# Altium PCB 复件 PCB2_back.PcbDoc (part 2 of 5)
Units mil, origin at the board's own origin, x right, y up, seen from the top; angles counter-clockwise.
Board outline 6299 x 3937 mil, 4 copper layers (TopLayer, GROUND, VCC, BottomLayer); 290 components, 470 nets, 2252 pads, 827 vias.
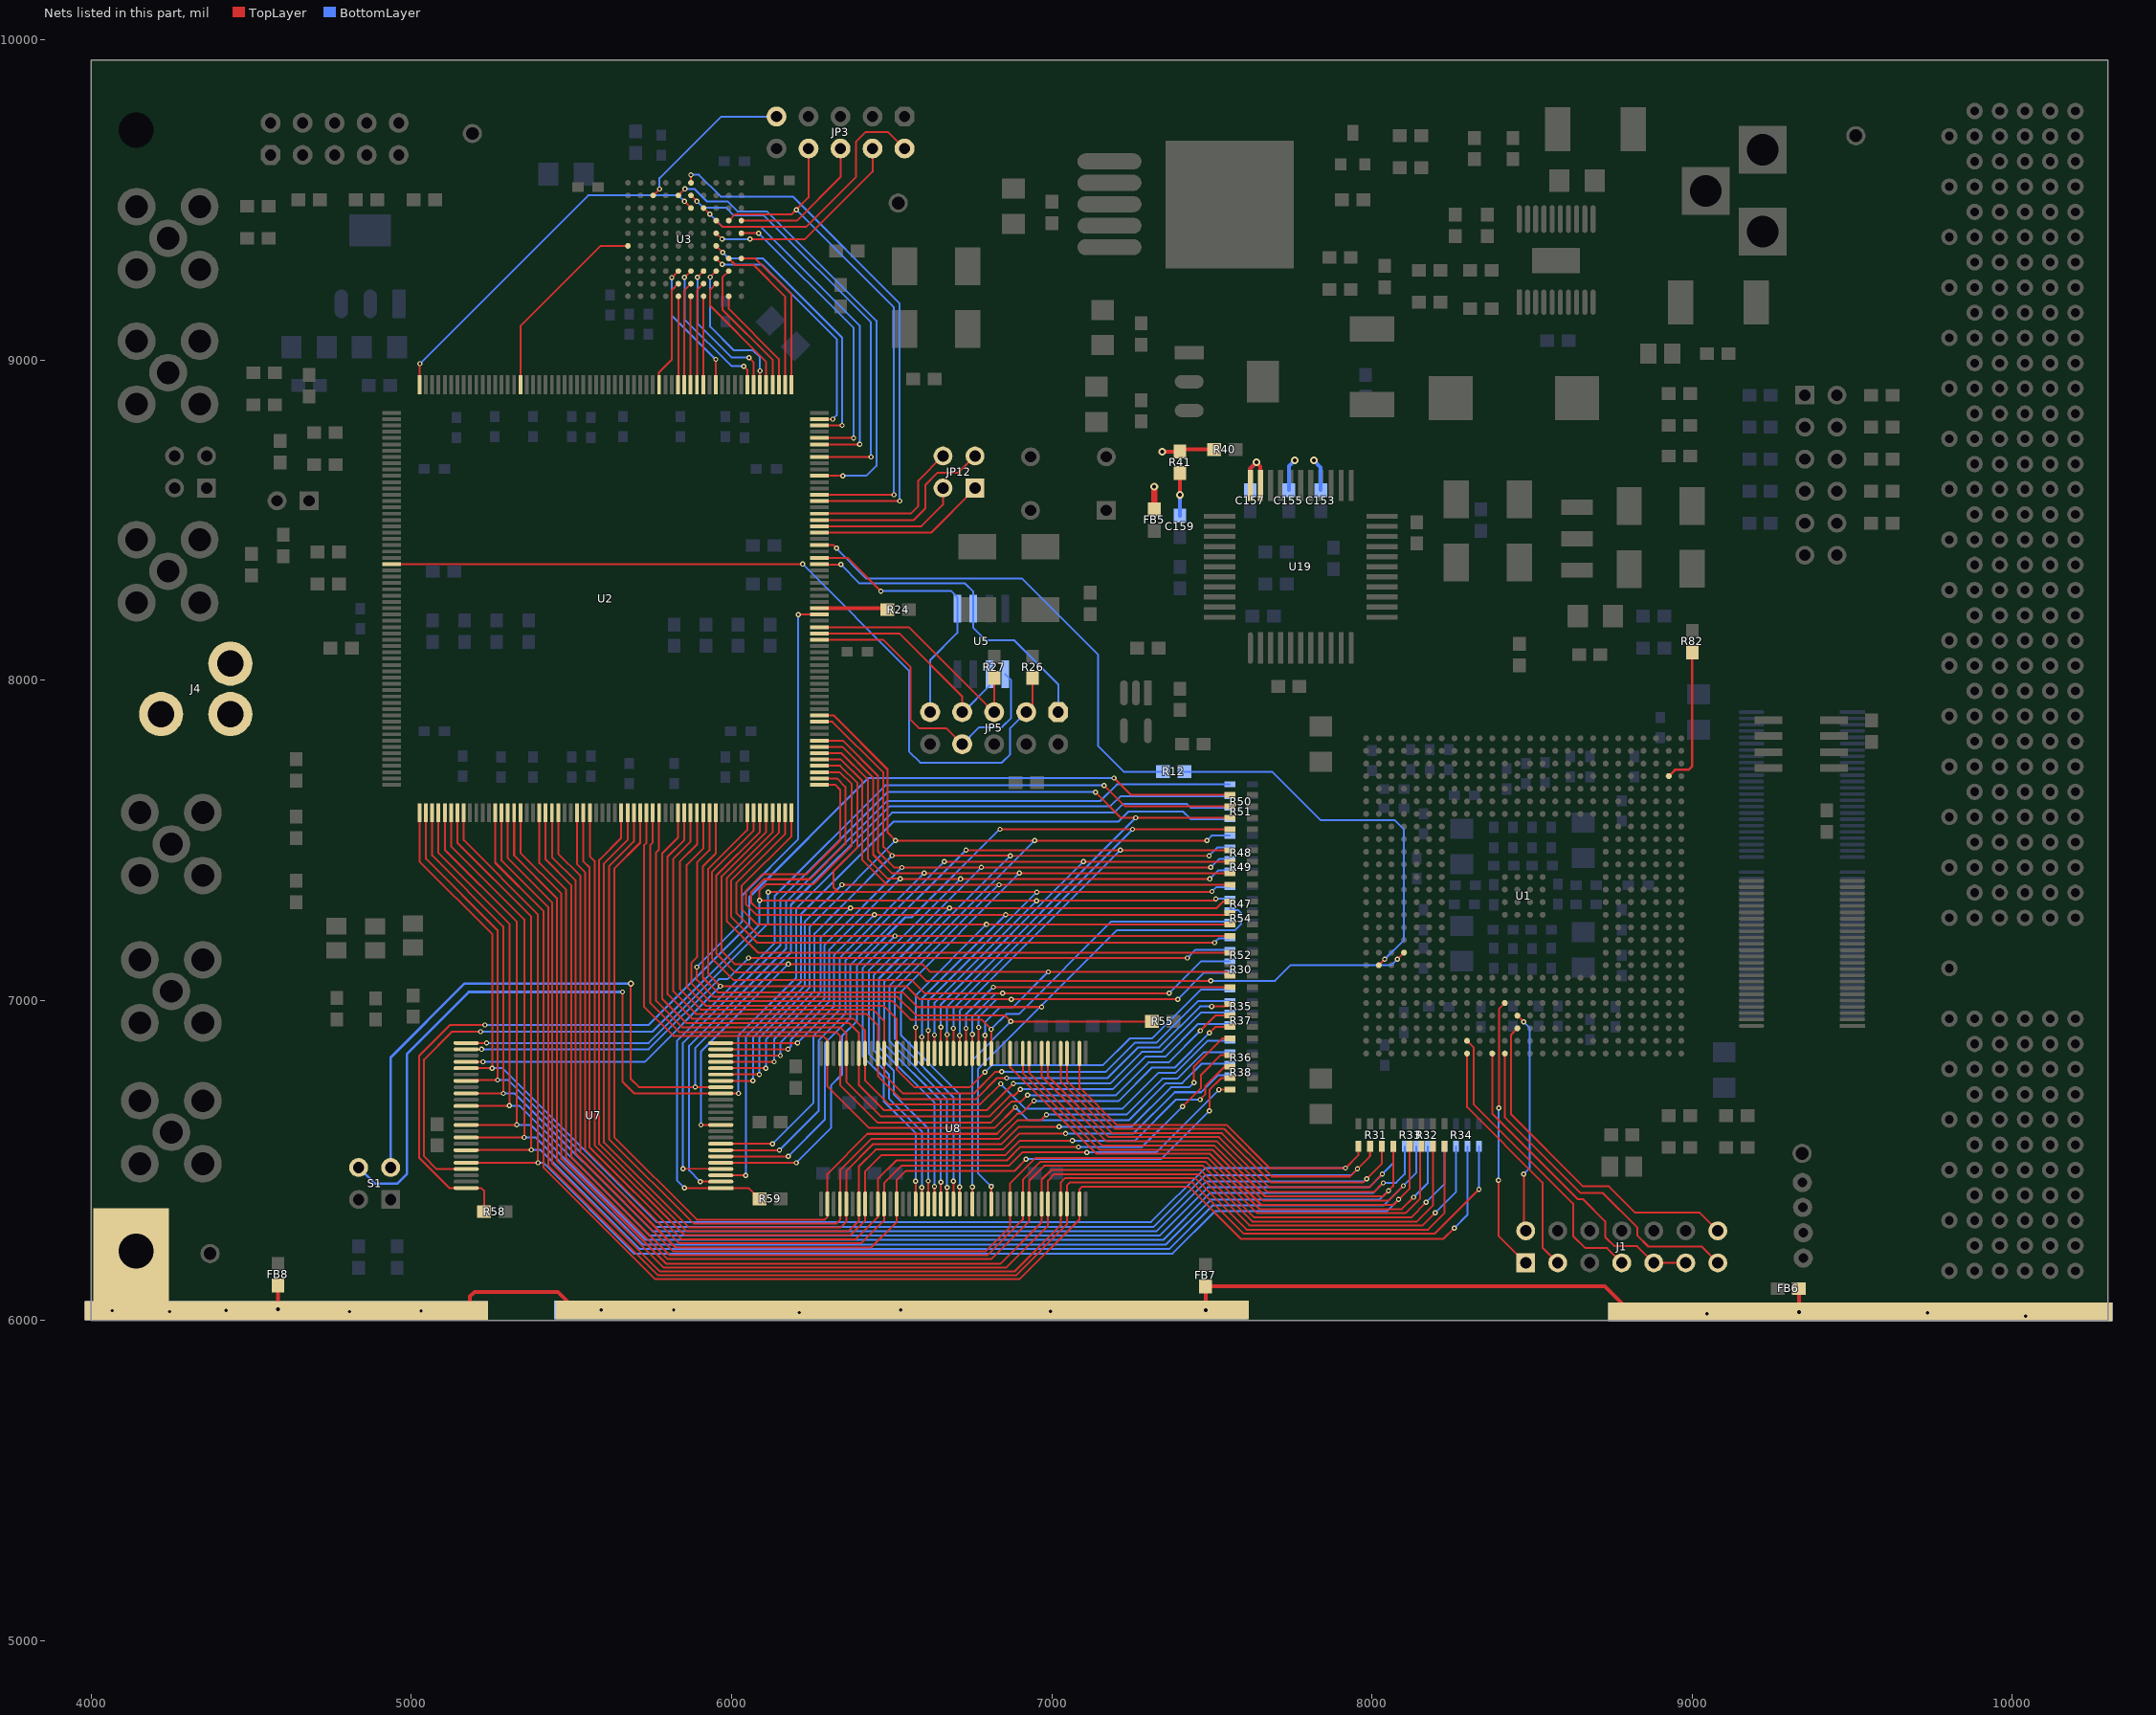
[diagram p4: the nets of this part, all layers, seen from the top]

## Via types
v1: diameter 16, hole 8, TopLayer to BottomLayer, 408 vias
v2: diameter 20, hole 10, TopLayer to BottomLayer, 220 vias
v3: diameter 24, hole 12, TopLayer to BottomLayer, 196 vias
v4: diameter 56.69, hole 56.69, TopLayer to BottomLayer, 2 vias
v5: diameter 20, hole 0, TopLayer to BottomLayer, 1 vias

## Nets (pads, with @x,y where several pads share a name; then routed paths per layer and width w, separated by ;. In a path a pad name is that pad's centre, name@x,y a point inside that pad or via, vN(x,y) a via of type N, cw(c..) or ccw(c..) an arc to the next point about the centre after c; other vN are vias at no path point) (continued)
101_RXST2: U2.104 U3.F1 | length 622.6
  TopLayer w6: U2.104@5340.25,8922.31 5340.25,9105.25 5591.15,9356.15 U3.F1@5676,9356.15
101_SCSEL: U2.63 U3.K9 | length 341.1
  TopLayer w6: U3.K9@5990.96,9198.67 5990.96,9159.04 6147.34,9002.66 U2.63@6147.34,8922.31
101_SDASEL: U2.120 U3.C6 | length 1147.2
  TopLayer w6: U2.120@5025.29,8922.31 5026,8923.02 v1(5026,8988) ; v1(5852.11,9495) U3.C6@5872.85,9474.26
  BottomLayer w6: v1(5026,8988) 5552,9514 5833.11,9514 v1(5852.11,9495)
101_SPDSEL: U2.55 U3.C7 | length 1136.3
  TopLayer w6: U3.C7@5912.22,9474.26 v1(5931.48,9455) ; U2.55@6274.31,8736.28 v1(6400,8736.28)
  BottomLayer w6: v1(5931.48,9455) 5971.48,9415 6092,9415 6400,9107 v1(6400,8736.28)
101_T\R\S\T\Z\: JP3.8 U2.47 U3.D9 | length 1680.7
  TopLayer w6: U3.D9@5990.96,9434.89 6011.07,9455 6188,9455 6240,9507 JP3.8@6240,9660 ; U2.47@6274.31,8578.8 v1(6507,8578.8)
  BottomLayer w6: v1(6202,9469) 6506,9165 ; v1(6507,8578.8) 6507,9165
101_T\X\R\S\T\: U2.64 U3.H9 | length 428.3
  TopLayer w6: U3.H9@5990.96,9277.41 5971,9257.45 5971,9157 6127.65,9000.35 U2.64@6127.65,8922.31
101_TCK: JP3.4 U3.E8 | length 655.5
  TopLayer w6: U3.E8@5951.59,9395.52 v1(5970.11,9377) ; v1(6057,9377) 6229,9377 6440,9588 JP3.4@6440,9660
  BottomLayer w6: v1(5970.11,9377) v1(6057,9377)
101_TDI: JP3.6 U3.D10 | length 455
  TopLayer w6: U3.D10@6030.33,9434.89 6203.89,9434.89 6340,9571 JP3.6@6340,9660
101_TDO: JP3.9 U3.B3 | length 507.3
  TopLayer w6: U3.B3@5754.74,9513.63 v1(5774.63,9533.52)
  BottomLayer w6: v1(5774.63,9533.52) 5774.63,9567.63 5967,9760 JP3.9@6140,9760
101_TMS: JP3.2 U3.D8 | length 804.8
  TopLayer w6: U3.D8@5951.59,9434.89 5971.48,9415 6232,9415 6389,9572 6389,9682 6418,9711 6489,9711 JP3.2@6540,9660
101_TXCKSEL: U2.56 U3.E10 | length 923.2
  TopLayer w6: U3.E10@6030.33,9395.52 v1(6084.48,9395.52) ; U2.56@6274.31,8755.97 v1(6381,8755.97)
  BottomLayer w6: v1(6084.48,9395.52) 6381,9099 v1(6381,8755.97)
101_TXCLK: U2.66 U3.H8 | length 461.7
  TopLayer w6: v1(5933,9258.82) U3.H8@5951.59,9277.41 ; U2.66@6088.28,8922.31 v1(6088.28,8965.72)
  BottomLayer w6: v1(5933,9258.82) 5933,9104 6007,9030 6066,9030 6088.28,9007.72 v1(6088.28,8965.72)
101_TXCLKO+: U2.62 U3.G9 | length 500.9
  TopLayer w6: U3.G9@5990.96,9316.78 6011.74,9296 6069,9296 6167.02,9197.98 U2.62@6167.02,8922.31
101_TXCLKO-: U2.61 U3.G10 | length 485
  TopLayer w6: U3.G10@6030.33,9316.78 6074.22,9316.78 6186.71,9204.29 U2.61@6186.71,8922.31
101_TXCT0: U2.82 U3.J5 | length 340.7
  TopLayer w6: U2.82@5773.32,8922.31 5773.32,8961.32 5813,9001 5813,9217.56 U3.J5@5833.48,9238.04
101_TXCT1: U2.73 U3.H5 | length 420.5
  TopLayer w6: v1(5813,9256.93) U3.H5@5833.48,9277.41 ; U2.73@5950.49,8922.31 v1(5950.49,9001.51)
  BottomLayer w6: v1(5813,9256.93) 5813,9139 v1(5950.49,9001.51)
101_TXD0: U2.65 U3.J8 | length 395.9
  TopLayer w6: U3.J8@5951.59,9238.04 5933,9219.45 5933,9169 6107.97,8994.03 U2.65@6107.97,8922.31
101_TXD1: U2.75 U3.K7 | length 276.8
  TopLayer w6: U2.75@5911.12,8922.31 5911.12,9197.57 U3.K7@5912.22,9198.67
101_TXD2: U2.76 U3.J7 | length 324.3
  TopLayer w6: U2.76@5891.43,8922.31 5891.43,9217.25 U3.J7@5912.22,9238.04
101_TXD3: U2.67 U3.H7 | length 466.8
  TopLayer w6: v1(5893,9258.19) U3.H7@5912.22,9277.41 ; v1(6054,9007) 6068.6,8992.4 U2.67@6068.6,8922.31
  BottomLayer w6: v1(5893,9258.19) 5893,9115 6001,9007 v1(6054,9007)
101_TXD4: U2.77 U3.K6 | length 276.8
  TopLayer w6: U2.77@5871.75,8922.31 5871.75,9197.57 U3.K6@5872.85,9198.67
101_TXD5: U2.78 U3.J6 | length 324.3
  TopLayer w6: U2.78@5852.06,8922.31 5852.06,9217.25 U3.J6@5872.85,9238.04
101_TXD6: U2.68 U3.H6 | length 466.7
  TopLayer w6: v1(5853,9257.56) U3.H6@5872.85,9277.41 ; v1(6038,8980) 6048.91,8969.09 U2.68@6048.91,8922.31
  BottomLayer w6: v1(5853,9257.56) 5853,9127 6000,8980 v1(6038,8980)
101_TXD7: U2.79 U3.K5 | length 278.4
  TopLayer w6: U2.79@5832.38,8922.31 5833.48,8923.41 U3.K5@5833.48,9198.67 U3.K5@5832.38,9197.57
101_TXMODE0: U2.53 U3.B6 | length 1307.2
  TopLayer w6: U3.B6@5872.85,9513.63 v1(5891.48,9495) ; U2.53@6274.31,8696.91 v1(6435,8696.91)
  BottomLayer w6: v1(5891.48,9495) 5910.48,9476 5982,9476 6007,9451 6101,9451 6435,9117 v1(6435,8696.91)
101_TXMODE1: U2.46 U3.A6 | length 1711
  TopLayer w6: U3.A6@5872.85,9553 v1(5872.85,9577.85) ; U2.46@6274.31,8559.12 v1(6525,8559.12)
  BottomLayer w6: v1(5872.85,9577.85) 5898,9577.85 5965.85,9510 6191,9510 6525,9176 v1(6525,8559.12)
101_TXOP: U2.59 U3.G8 | length 777.4
  TopLayer w6: U3.G8@5951.59,9316.78 v1(5970.37,9298) ; U2.59@6274.31,8815.02 v1(6316.02,8815.02)
  BottomLayer w6: v1(5970.37,9298) 6095,9298 6328,9065 6328,8827 v1(6316.02,8815.02)
101_TXPER: U2.58 U3.F8 | length 857.3
  TopLayer w6: U3.F8@5951.59,9356.15 v1(5971.74,9336) ; U2.58@6274.31,8795.34 v1(6345,8795.34)
  BottomLayer w6: v1(5971.74,9336) 5990.74,9317 6098,9317 6345,9070 v1(6345,8795.34)
101_TXRATE: U2.50 U3.B5 | length 1441.1
  TopLayer w6: U3.B5@5833.48,9513.63 v1(5853.7,9533.85) ; U2.50@6274.31,8637.86 v1(6346.86,8637.86)
  BottomLayer w6: v1(5853.7,9533.85) 5883.15,9533.85 5922,9495 5987,9495 6018,9464 6110,9464 6452,9122 6452,8669 6420.86,8637.86 v1(6346.86,8637.86)
AGND: C153.1 C155.1 C157.1 C159.1 FB5.1 J4.2 R41.1 U19.32 U19.33 | length 657.9
  TopLayer w12: v3(7400,8578) R41.1@7400,8646.54 ; U19.33@7620,8607.87 7620,8661 v3(7639,8680) 7651.5,8667.5 U19.32@7651.5,8607.87
  TopLayer w20: FB5.1@7320,8533.46 v3(7320,8604)
  BottomLayer w12: C159.1@7400,8513.46 v3(7400,8578) ; C157.1@7620,8593.46 7620,8661 v3(7639,8680) ; C155.1@7740,8593.46 7740,8669 v3(7758,8687) ; v3(7818,8686) 7840,8664 C153.1@7840,8593.46
AOE#: R52.6 U2.234 U8.19 | length 2452.6
  TopLayer w6: U2.234@6068.6,7585.69 6068.6,7530.6 5938,7400 5938,7131 6005,7064 6561,7064 6603,7022 v1(7366,7022) ; U8.19@6751.67,6834 v1(6751.67,6893.67)
  BottomLayer w6: v1(6751.67,6893.67) 6751.67,6948.67 6825,7022 v1(6846,7022) ; v1(7366,7022) 7466,7122 R52.6@7555.84,7122
ARE#: R52.5 U2.233 U7.28 U8.18 | length 3381.2
  TopLayer w6: U7.28@5170.72,6807.7 v1(5223.7,6807.7) ; U2.233@6048.91,7585.69 6048.91,7531.91 5926,7409 5926,7083 v1(5965,7044) 6546,7044 6587,7003 v1(7393,7003) ; U8.18@6771.35,6834 v1(6771.35,6915.35)
  BottomLayer w6: v1(5223.7,6807.7) 5728.7,6807.7 v1(5965,7044) ; v1(6771.35,6915.35) 6771.35,6947.35 6827,7003 v1(6873,7003) ; v1(7393,7003) 7476,7086 R52.5@7555.84,7086
AS_CONFDN: JP5.3 R26.1 U2.145 | length 2615.7
  TopLayer w6: U2.145@4937.69,8362.27 v1(6221.73,8362.27) ; JP5.3@6920,7900 6940,7920 R26.1@6940,8006.54
  BottomLayer w6: v1(6221.73,8362.27) 6554,8030 6554,7777 6589,7742 6844,7742 6870,7768 6870,7850 JP5.3@6920,7900
AS_DCLK: JP5.1 U2.36 U5.6 | length 1054.3
  TopLayer w6: U2.36@6274.31,8362.27 6275.57,8361 v1(6341,8361)
  BottomLayer w6: v1(6341,8361) 6400,8302 6729,8302 6755,8276 6755,8163 6794,8124 6883,8124 7020,7987 JP5.1@7020,7900
AS_NCONFIG: JP5.5 R27.1 U2.26 | length 762.2
  TopLayer w6: U2.26@6274.31,8165.42 6553.58,8165.42 6819,7900 JP5.5@6820,7900 R27.1@6820,8006.54
AWE#: R30.7 U2.236 U7.11 U8.17 | length 3145.4
  TopLayer w6: v1(5904.15,6610.85) U7.11@5966,6610.85 ; U2.236@6107.97,7585.69 6107.97,7525.97 5969,7387 5969,7154 6010,7113 6595,7113 6619,7089 7543.84,7089 R30.7@7555.84,7077 ; U8.17@6791.04,6834 v1(6791.04,6891.04)
  BottomLayer w6: v1(5904.15,6610.85) 5904.15,6840.15 v1(6177,7113) ; v1(6791.04,6891.04) 6791.04,6931.04 6838.94,6978.94 6878.94,6978.94 v1(6989,7089)
BE0#: R47.5 U2.227 U8.16 | length 2511.8
  TopLayer w6: U2.227@5930.8,7585.69 5930.8,7468.8 5892,7430 5892,7135 5874,7117 5874,7054 5930,6998 6501,6998 6559,6940 6780.45,6940 v1(6810.73,6909.73) U8.16@6810.73,6834
  BottomLayer w6: v1(6810.73,6909.73) 6859,6958 6898,6958 7186,7246 R47.5@7555.84,7246
BE1#: R47.6 U2.228 U8.71 | length 3156
  TopLayer w6: U2.228@5950.49,7585.69 5950.49,7458.49 5910,7418 5910,7071 5956,7025 6534,7025 6580,6979 v1(6968,6979) ; U8.71@6810.73,6364 v1(6810.73,6418.73)
  BottomLayer w6: v1@6816,6424 v1(6810.73,6418.73) 6770,6459.45 6770,6786 7203,7219 7572,7219 7591,7238 7591,7273 7582,7282 R47.6@7555.84,7282
BE2#: R54.7 U2.240 U8.28 | length 2404.7
  TopLayer w6: U2.240@6186.71,7585.69 6186.71,7512.71 6031,7357 6031,7285 6079,7237 R54.7@7555.84,7237 ; U8.28@6574.51,6834 v1(6574.51,6915.51)
  BottomLayer w6: v1(6574.51,6915.51) 6574.51,7015.51 v1(6796,7237)
BE3#: R54.8 U2.239 U8.59 | length 2895.1
  TopLayer w6: U2.239@6167.02,7585.69 6167.02,7519.02 6014,7366 6014,7273 6086,7201 R54.8@7555.84,7201 ; U8.59@6574.51,6364 v1(6574.51,6435.51)
  BottomLayer w6: v1(6510,7201) 6409,7100 6409,6825 6475,6759 6475,6685 6574.51,6585.49 v1(6574.51,6435.51)
CE0#: R30.8 U8.20 | length 981.1
  TopLayer w6: U8.20@6731.98,6834 v1(6731.98,6912.31) ; v1(6817,7041) R30.8@7555.84,7041
  BottomLayer w6: v1(6731.98,6912.31) 6731.98,6955.98 v1(6817,7041)
CE1#: R52.7 U7.26 | length 2513.9
  TopLayer w6: U7.26@5170.72,6847.07 v1(5219,6847) ; v1(6053,7132) v1(7423,7132)
  BottomLayer w6: v1(5219,6847) 5576.07,6847.07 5741.07,6847.07 5960,7066 5987,7066 v1(6053,7132) ; v1(7423,7132) 7449,7158 R52.7@7555.84,7158
CE2#: R52.8 U2.238 | length 1983.2
  TopLayer w6: U2.238@6147.34,7585.69 6147.34,7523.34 5998,7374 5998,7262 6080,7180 v1(7508,7180)
  BottomLayer w6: v1(7508,7180) 7522,7194 R52.8@7555.84,7194
CE3#: R30.5 U2.237 | length 2009.8
  TopLayer w6: U2.237@6127.65,7585.69 6127.65,7524.65 5985,7382 5985,7246 6082,7149 R30.5@7555.84,7149
CVBS: J4.1 R40.2 R41.2 | length 164.7
  TopLayer w12: v3(7344.54,8713.46) R41.2@7400,8713.46 7406.54,8720 R40.2@7506.54,8720
DATA: JP5.7 U2.25 U5.2 | length 730.8
  TopLayer w6: U2.25@6274.31,8145.73 6523.27,8145.73 6720,7949 JP5.7@6720,7900
  BottomLayer w6: JP5.7@6720,7900 6723,7900 6805,7982 U5.2@6805,8017.64
DSP_CLKIN: R82.2 U1.AC2 | length 441.7
  TopLayer w8: U1.AC2@8926.63,7700.14 8946.49,7720 8989,7720 9000,7731 R82.2@9000,8086.54
DSP_T\R\S\T\: J1.2 U1.D14 | length 697.7
  TopLayer w6: U1.D14@8454.19,6952.11 v1(8474,6932.3) ; v1(8474,6457) 8474,6286 J1.2@8480,6280
  BottomLayer w6: v1(8474,6457) 8492,6475 8492,6914.3 v1(8474,6932.3)
DSP_TCLK: J1.9 J1.11 U1.A16 | length 1014
  TopLayer w6: U1.A16@8375.45,6834 8375.45,6646.55 8643,6379 8659,6379 8728,6310 8728,6261 8757,6232 8828,6232 J1.9@8880,6180 J1.11@8980,6180
DSP_TDI: J1.3 U1.A18 | length 771.3
  TopLayer w6: U1.A18@8296.71,6834 8296.71,6666.29 8532,6431 8532,6228 J1.3@8580,6180
DSP_TDO: J1.7 U1.B18 | length 933.4
  TopLayer w6: U1.B18@8296.71,6873.37 8317,6853.08 8317,6676 8628,6365 8628,6264 8666,6226 8734,6226 J1.7@8780,6180
DSP_TMS: J1.1 U1.E15 | length 854.9
  TopLayer w6: v1(8395,6438) 8395,6265 J1.1@8480,6180 ; v1(8396,6664) 8396,6972.66 U1.E15@8414.82,6991.48
  BottomLayer w6: v1(8395,6438) 8395,6663 v1(8396,6664)
EA03: R47.7 U2.3 U7.45 U8.25 | length 4512.2
  TopLayer w6: U7.45@5170.72,6473.06 5078.94,6473.06 5039,6513 5039,6815 5126,6902 v1(5216,6902) ; v1(6087,7312) 6087,7343 6106,7362 6254,7362 6375,7483 6375,7675 6337.34,7712.66 U2.3@6274.31,7712.66 ; v1@6088,7311 7506,7311 v1(7512,7317) ; U8.25@6633.56,6834 v1(6633.56,6891.56)
  BottomLayer w6: v1(5216,6902) 5753,6902 6087,7236 v1(6087,7312) ; v1(6633.56,6891.56) 6633.56,6992.56 v1(6952,7311) ; v1(7512,7317) R47.7@7554.84,7317
EA04: R47.8 U2.4 U7.25 U8.26 | length 3807.3
  TopLayer w6: U7.25@5170.72,6866.76 v1(5234.76,6866.76) ; v1(6114,7338) 7498,7338 v1(7500,7340) ; U2.4@6274.31,7732.35 6338.65,7732.35 6393,7678 6393,7478 6318,7403 6318,7353 6333,7338 ; U8.26@6613.88,6834 v1(6613.88,6905.31)
  BottomLayer w6: v1(5234.76,6866.76) 5740.76,6866.76 6114,7240 v1(6114,7338) ; v1(6613.88,6905.31) 6613.88,6998.88 v1(6953,7338) ; v1(7500,7340) 7514,7354 R47.8@7555.84,7354
EA05: R54.6 U2.1 U7.24 U8.27 | length 3440.2
  TopLayer w6: U7.24@5966,6866.76 v1(6205.76,6866.76) ; U2.1@6274.31,7673.29 6323.71,7673.29 6339,7658 6339,7499 6233,7393 6095,7393 6045,7343 6045,7299 6077,7267 7549.84,7267 R54.6@7555.84,7273 ; U8.27@6594.19,6834 v1(6594.19,6885.63)
  BottomLayer w6: v1(6205.76,6866.76) 6319,6980 6319,7140 v1(6446,7267) ; v1(6594.19,6885.63) 6594.19,7005.19 v1(6856,7267)
EA06: R48.5 U2.6 U7.23 U8.60 | length 3691.2
  TopLayer w6: U7.23@5966,6847.07 v1(6176.07,6847.07) ; U2.6@6274.31,7771.72 6343.28,7771.72 6425,7690 6425,7442 6487.1,7379.9 v1(6526.9,7379.9) ; v1@6526.9,7379 v1(7493,7379) ; U8.60@6594.19,6364 v1(6594.19,6415.19)
  BottomLayer w6: v1(6176.07,6847.07) 6185,6856 6185,6877 6305,6997 6305,7158 v1(6526.9,7379.9) ; v1(6594.19,6415.19) 6594.19,6591 6491,6694.19 6491,6769 6428,6832 6428,7092 v1(6715,7379) ; v1(7493,7379) 7520,7406 R48.5@7555.84,7406
EA07: R48.6 U2.8 U7.22 U8.61 | length 3786.6
  TopLayer w6: U7.22@5966,6827.39 v1(6152.39,6827.39) ; U2.8@6274.31,7811.09 6346.91,7811.09 6457,7701 6457,7465 6507.19,7414.81 v1(6531.81,7414.81) ; v1@6531.81,7415 v1(7496,7415) ; U8.61@6613.88,6364 v1(6613.88,6435.88)
  BottomLayer w6: v1(6152.39,6827.39) 6152.39,6868.39 6290,7006 6290,7173 v1(6531.81,7414.81) ; v1(6613.88,6435.88) 6613.88,6599 6506,6706.88 6506,6781 6444,6843 6444,7079 v1(6780,7415) ; v1(7496,7415) 7523,7442 R48.6@7555.84,7442
EA08: R54.5 U2.2 U7.21 U8.62 | length 4002.9
  TopLayer w6: U7.21@5966,6807.7 v1(6132.7,6807.7) ; U2.2@6274.31,7692.98 6329.02,7692.98 6355,7667 6355,7488 6245,7378 6101,7378 6061,7338 6061,7305 6078,7288 7515,7288 7536,7309 R54.5@7555.84,7309 ; U8.62@6633.56,6364 v1(6633.56,6418.56)
  BottomLayer w6: v1(6132.7,6807.7) 6132.7,6879 6277,7023.3 6277,7194 v1(6371,7288) ; v1(6633.56,6418.56) 6633.56,6680.44 6460,6854 6460,7068 v1(6680,7288)
EA09: R48.7 U2.11 U7.20 U8.63 | length 3901.4
  TopLayer w6: U7.20@5966,6788.02 v1(6107.02,6788.02) ; U2.11@6274.31,7870.14 6314.86,7870.14 6474,7711 6474,7479 v1(6501,7452) 6870,7451.63 v1(7491,7451) ; U8.63@6653.24,6364 v1(6653.24,6431.76)
  BottomLayer w6: v1(6107.02,6788.02) 6107.02,6878.02 6259,7030 6259,7208 6342,7291 ; 6341.2,7291.8 v1(6501,7452) ; v1(6653.24,6431.76) 6653.24,6686.76 6477,6863 6477,7058 v1(6870,7451) ; v1(7491,7451) 7518,7478 R48.7@7565,7478
EA10: R48.8 U2.12 U7.19 U8.64 | length 3989.2
  TopLayer w6: U7.19@5966,6768.33 v1(6086.33,6768.33) ; U2.12@6274.31,7889.83 6318.17,7889.83 6487,7721 6487,7524 v1(6512,7499) v1(7484,7499) ; U8.64@6672.93,6364 v1(6672.93,6416.07)
  BottomLayer w6: v1(6086.33,6768.33) 6086.33,6882 6244,7039.67 6244,7230 6271,7257 ; 6270.78,7257.22 v1(6512,7499) ; v1(6672.93,6416.07) 6672.93,6691.07 6493,6871 6493,7046 v1(6946,7499) ; v1(7484,7499) 7499,7514 R48.8@7555.84,7514
EA11: R49.8 U2.5 U7.18 U8.65 | length 3801.3
  TopLayer w6: U7.18@5966,6748.65 v1(6066.65,6748.65) ; U2.5@6274.31,7752.03 6340.97,7752.03 6408,7685 6408,7438 6485,7361 6522,7361 ; v1(6343.82,7360.82) 6522,7360.85 6835,7360.9 R49.8@7555.84,7361 ; U8.65@6692.61,6364 v1(6692.61,6435.39)
  BottomLayer w6: v1(6066.65,6748.65) 6066.65,6883.65 6229,7046 6229,7246 v1(6343.82,7360.82) ; v1(6692.61,6435.39) 6692.61,6697.39 6510,6880 6510,7036 v1(6835,7361)
EA12: R49.7 U2.7 U7.8 U8.66 | length 4050.1
  TopLayer w6: U7.8@5966,6551.8 v1(6127.8,6551.8) ; U2.7@6274.31,7791.4 6345.6,7791.4 6442,7695 6442,7455 6500,7397 R49.7@7555.84,7397 ; U8.66@6712.3,6364 v1(6712.3,6416.7)
  BottomLayer w6: v1(6127.8,6551.8) 6255,6679 6255,6888 6337,6970 6337,7131 6364,7158 ; 6363.31,7158.68 v1(6601,7397) ; v1(6712.3,6416.7) 6712.3,6706.7 6529,6890 6529,7027 v1(6899,7397)
EA13: R49.6 U7.7 U8.24 | length 2972.8
  TopLayer w6: U7.7@5966,6532.11 v1(6149.11,6532.11) ; U8.24@6653.24,6834 v1(6653.24,6916.24) ; v1(6664,7433) R49.6@7555.84,7433
  BottomLayer w6: v1(6149.11,6532.11) 6271,6654 6271,6874 6355,6958 6355,7124 v1(6664,7433) ; v1(6653.24,6916.24) 6653.24,6987.24 v1(7099,7433)
EA14: R49.5 U7.6 U8.21 | length 3064.4
  TopLayer w6: U7.6@5966,6512.43 v1(6176.43,6512.43) ; U8.21@6712.3,6834 v1(6712.3,6890.3) ; v1(6732,7469) R49.5@7555.84,7469
  BottomLayer w6: v1(6176.43,6512.43) 6291,6627 6291,6866 6371,6946 6371,7110 6415,7154 ; 6415.33,7153.66 v1(6732,7469) ; v1(6712.3,6890.3) 6712.3,6967.3 v1(7214,7469)
EA15: R51.8 U7.5 U8.22 | length 3200
  TopLayer w6: U7.5@5966,6492.74 v1(6201.74,6492.74) ; U8.22@6692.61,6834 v1(6692.61,6912.61) ; v1(6838,7534) R51.8@7555.84,7534
  BottomLayer w6: v1(6201.74,6492.74) 6310,6601 6310,6734 6345,6769 6345,6889 6392,6936 6392,7109 6542.23,7259.23 6562.23,7259.23 v1@6836,7533 ; v1(6692.61,6912.61) 6692.61,6974.61 v1(7252,7534)
EA16: R51.7 U7.4 U8.23 | length 3640.7
  TopLayer w6: v1(5848,6474) U7.4@5966,6473.06 ; U8.23@6672.93,6834 v1(6672.93,6892.93) ; v1(7136,7650) 7216,7570 R51.7@7555.84,7570
  BottomLayer w6: v1(5848,6474) 5848,6867 6152,7171 6152,7315 6487,7650 v1(7136,7650) ; v1(6672.93,6892.93) 6672.93,6980.93 v1(7262,7570)
EA17: R50.5 U7.3 | length 2447.6
  TopLayer w6: U7.3@5966,6453.37 v1(6043.96,6453.37)
  BottomLayer w6: v1(6043.96,6453.37) 6043.96,6886 6216.46,7058.5 6216.46,7269.46 6505,7558 7208,7558 7240,7590 7409,7590 7433,7566 R50.5@7555.84,7566
EA18: R50.8 U7.2 | length 2615
  TopLayer w6: v1(5902.31,6433.69) U7.2@5966,6433.69
  BottomLayer w6: v1(5902.31,6433.69) 5867,6469 5867,6858 6169.54,7160.54 6169.54,7306.54 6486,7623 7152,7623 7203,7674 R50.8@7555.84,7674
EA19: R51.6 R59.2 U7.1 | length 2887
  TopLayer w6: v1(5853,6414) 6052.54,6414 R59.2@6086.54,6380 ; v1(7163,7671) 7228,7606 R51.6@7555.84,7606
  BottomLayer w6: v1(5853,6414) 5829,6438 5829,6873 6134,7178 6134,7325 6480,7671 v1(7163,7671)
EA20: R51.5 R58.1 U7.48 | length 3591.8
  TopLayer w6: R58.1@5226.54,6340 5226.54,6405.46 5218,6414 5118,6414 5024,6508 5024,6827 5120,6923 v1(5229,6923) ; v1(7194,7694) 7246,7642 R51.5@7555.84,7642
  BottomLayer w6: v1(5229,6923) 5741,6923 6055,7237 6055,7322 6427,7694 v1(7194,7694)
EA21: R50.7 S1.3 U7.17 | length 4000.2
  TopLayer w6: v2(5685,7052) 5685,6754 5710.04,6728.96 U7.17@5966,6728.96
  BottomLayer w6: v1(5886.04,6728.96) 5886.04,6851.04 6185,7150 6185,7298 6493,7606 7183,7606 7215,7638 R50.7@7555.84,7638
  BottomLayer w8: S1.3@4923,6490 S1.3@4935,6478 4935,6822 5165,7052 v2(5685,7052)
EA22: R50.6 S1.4 U7.16 | length 4116.4
  TopLayer w6: v1(5659,7026) 5659,6746.27 5696,6709.27 ; 5695,6709 5966,6709.23 v1(6021.27,6709.27)
  BottomLayer w6: v1(6021.27,6709.27) 6021.27,6890.27 6202,7071 6202,7287 6501,7586 7194,7586 7221,7613 7422,7613 7433,7602 R50.6@7555.84,7602
  BottomLayer w8: S1.4@4835,6478 4885,6428 4956,6428 4986,6458 4986,6833 5179,7026 v1(5659,7026)
ECLKIN: R12.2 U1.H25 | length 1217.6
  TopLayer w6: U1.H25@8021.12,7109.59 v1(8039.53,7128)
  BottomLayer w6: R12.2@7413.46,7714 7688,7714 7839,7563 8070,7563 8100,7533 8100,7188.47 v1(8039.53,7128)
ECLKOUT1: R55.2 U2.28 U8.68 | length 3433.6
  TopLayer w6: v1(5891,7104) 5891,7064 5944,7011 6518,7011 6576,6953 6853,6953 v1(6872,6934) R55.2@7312.54,6934 ; v1(6208,8204.79) U2.28@6274.31,8204.79 ; U8.68@6751.67,6364 v1(6751.67,6416.67)
  BottomLayer w6: v1(5891,7104) 6033,7246 6033,7328 6208,7503 v1(6208,8204.79) ; v1(6751.67,6416.67) 6751.67,6813.67 v1(6872,6934)
ECLKOUT2: U1.J23 U2.235 | length 2715.6
  TopLayer w6: U2.235@6088.28,7585.69 6088.28,7526.28 5952,7390 5952,7146 6010,7088 6580,7088 6607,7061 v1(7496,7061) ; v1(8078.9,7128) U1.J23@8099.86,7148.96
  BottomLayer w6: v1(7496,7061) 7697,7061 7746,7110 8060.9,7110 v1(8078.9,7128)
ED00: R31.5 U2.181 U7.29 U8.2 | length 5032.4
  TopLayer w6: U2.181@5025.29,7585.69 5025.29,7433.71 5252,7207 v1(5252,6788) U7.29@5170.72,6788.02 ; U8.2@7086.31,6834 7086.31,6727.69 7204,6610 7547,6610 7681,6476 v1(7917,6476) 7958,6517 R31.5@7958,6543.84
  BottomLayer w6: v1(5252,6788) 5284.98,6788.02 5765,6308 7310,6308 7478,6476 v1(7917,6476)
ED01: R31.6 U2.182 U7.31 U8.4 | length 5188.6
  TopLayer w6: U2.182@5044.98,7585.69 5044.98,7442.02 5269,7218 v1(5269,6751) U7.31@5173.08,6751 ; U7.31@5170.72,6748.65 U7.31@5173.08,6748.65 ; U8.4@7046.94,6834 7046.94,6749.06 7198,6598 7539,6598 7687,6450 7931,6450 7994,6513 R31.6@7994,6543.84
  BottomLayer w6: v1(5269,6751) 5303,6751 5761,6293 7318,6293 7478,6453 7934,6453 v1(7954.5,6473.5)
ED02: R31.7 U2.183 U7.33 U8.5 | length 5326.7
  TopLayer w6: U2.183@5064.66,7585.69 5064.66,7452.34 5286.73,7230.27 v1(5286.73,6709.27) U7.33@5170.72,6709.27 ; U8.5@7027.26,6834 7027.26,6746.74 7188.95,6585.05 7530.95,6585.05 7684,6432 7973,6432 8030,6489 R31.7@8030,6543.84
  BottomLayer w6: v1(5286.73,6709.27) 5321.73,6709.27 5752,6279 7327,6279 7483,6435 7976,6435 v1(7984,6443)
ED03: R33.8 U2.184 U7.35 U8.7 | length 5492.6
  TopLayer w6: U2.184@5084.35,7585.69 5084.35,7460.65 5306,7239 v1(5306,6671) 5171.82,6671 U7.35@5170.72,6669.9 ; U8.7@6987.89,6834 6987.89,6763.11 7178.14,6572.86 7522.14,6572.86 7679,6416 7991,6416 v1(8032,6457)
  BottomLayer w6: v1(5306,6671) 5337,6671 5743,6265 7336,6265 7487,6416 7991,6416 8066,6491 R33.8@8066,6543.84
ED04: R33.7 U2.185 U7.38 U8.8 | length 5619.2
  TopLayer w6: U2.185@5104.03,7585.69 5104.03,7469.97 5329,7245 v1(5329,6611) U7.38@5170.72,6610.85 ; U8.8@6968.2,6834 6968.2,6761.8 7170.75,6559.25 7515.75,6559.25 7673,6402 8007,6402 v1(8035,6430)
  BottomLayer w6: v1(5329,6611) 5372.15,6610.85 5731,6252 7348,6252 7494,6398 8003,6398 v1(8035,6430) 8075,6430 8102,6457 R33.7@8102,6543.84
ED05: R31.8 U2.186 U7.40 U8.10 | length 5691.8
  TopLayer w6: U2.186@5123.72,7585.69 5123.72,7481.28 5352,7253 v1(5352,6572) 5171.24,6572 U7.40@5170.72,6571.48 ; U8.10@6928.84,6834 6928.84,6774.16 7157,6546 7508,6546 7666,6388 8034,6388 8066,6420 R31.8@8066,6543.84
  BottomLayer w6: v1(5352,6572) 5387,6572 5722,6237 7356,6237 7496,6377 8023,6377 v1(8051.45,6405.45)
ED06: R33.6 U2.187 U7.42 U8.11 | length 5860.4
  TopLayer w6: U2.187@5143.4,7585.69 5143.4,7491.6 5374,7261 v1(5374,6533) 5171.61,6533 U7.42@5170.72,6532.11 ; U8.11@6909.15,6834 6909.15,6772.85 7148.53,6533.47 7501.53,6533.47 7661,6374 8051,6374 v1(8098,6421)
  BottomLayer w6: v1(5374,6533) 5403,6533 5713,6223 7366,6223 7503,6360 8037,6360 8138,6461 R33.6@8138,6543.84
ED07: R32.5 U2.188 U7.44 U8.13 | length 5911.6
  TopLayer w6: U2.188@5163.09,7585.69 5163.09,7499.91 5395,7268 v1(5395,6492.74) U7.44@5170.72,6492.74 ; U8.13@6869.78,6834 6869.78,6790.22 7139,6521 7494,6521 7654,6361 8067,6361 8118,6412 R32.5@8118,6543.84
  BottomLayer w6: v1(5395,6492.74) 5411.26,6492.74 5695,6209 7377,6209 7509,6341 8046,6341 v1(8083,6378)
ED08: R33.5 U2.202 U8.74 | length 4298.1
  TopLayer w6: U2.202@5438.68,7585.69 5438.68,7447.32 5513,7373 5513,6521 5818,6216 6793,6216 6869.78,6292.78 6869.78,6428.78 6949,6508 7488,6508 7648,6348 8093,6348 v1(8130,6385)
  BottomLayer w6: v1(8130,6385) 8174,6429 R33.5@8174,6543.84
ED09: R32.6 U2.201 U8.76 | length 4330.4
  TopLayer w6: U2.201@5418.99,7585.69 5418.99,7440.01 5499,7360 5499,6512 5807,6204 6798,6204 6909.15,6315.15 6909.15,6440.15 6965,6496 7480,6496 7641,6335 8105,6335 8150,6380 8150,6539.84 R32.6@8154,6543.84
ED10: R34.8 U2.200 U8.77 | length 4407.6
  TopLayer w6: U2.200@5399.31,7585.69 5399.31,7428.69 5482,7346 5482,6510 5800,6192 6811,6192 6928.84,6309.84 6928.84,6435.84 6976,6483 7472,6483 7633,6322 8122,6322 v1(8169,6369)
  BottomLayer w6: v1(8169,6369) 8226,6426 R34.8@8226,6543.84
ED11: R32.7 U2.197 U8.79 | length 4462.9
  TopLayer w6: U2.197@5340.25,7585.69 5340.25,7460.75 5468,7333 5468,6505 5795,6178 6840.2,6178 6968.2,6306 6968.2,6440.2 6998,6470 7465,6470 7626,6309 8140,6309 8190,6359 R32.7@8190,6543.84
ED12: R34.7 U2.196 U8.80 | length 4544.1
  TopLayer w6: U2.196@5320.57,7585.69 5320.57,7452.43 5454,7319 5454,6499 5788,6165 6857,6165 6987.89,6295.89 6987.89,6436.89 7008,6457 7457,6457 7617,6297 8158,6297 v1(8197,6336)
  BottomLayer w6: v1(8197,6336) 8262,6401 R34.7@8262,6543.84
ED13: R32.8 U2.195 U8.82 | length 4575
  TopLayer w6: U2.195@5300.88,7585.69 5300.88,7444.12 5440,7305 5440,6489 5776,6153 6883,6153 7027.26,6297.26 7027.26,6430.26 7042,6445 7447,6445 7608,6284 8175,6284 8226,6335 R32.8@8226,6543.84
ED14: R34.5 U2.194 U8.83 | length 4659.9
  TopLayer w6: U2.194@5281.2,7585.69 5281.2,7436.8 5427,7291 5427,6485 5771,6141 6888,6141 7046.94,6299.94 7046.94,6421.94 7056,6431 7440,6431 7600,6271 8195,6271 v1(8334,6410)
  BottomLayer w6: v1(8334,6410) R34.5@8334,6543.84
ED15: R34.6 U2.193 U8.85 | length 4687.8
  TopLayer w6: U2.193@5261.51,7585.69 5261.51,7429.49 5413,7278 5413,6477 5761,6129 6899,6129 7086.31,6316.31 7086.31,6410.31 7094,6418 7428,6418 7591,6255 8223,6255 v1(8257,6289)
  BottomLayer w6: v1(8257,6289) 8298,6330 R34.6@8298,6543.84
ED16: R35.8 U2.226 U8.31 | length 2610.1
  TopLayer w6: U2.226@5911.12,7585.69 5911.12,7474.12 5860,7423 5860,7042 5919,6983 6474,6983 6515.45,6941.55 6515.45,6783.55 6571,6728 6743,6728 v1(6791,6776)
  BottomLayer w6: v1(6791,6776) 6812,6797 7159,6797 7243,6881 7313,6881 7466,7034 R35.8@7555.84,7034
ED17: R35.7 U2.225 U8.33 | length 2643.2
  TopLayer w6: U2.225@5891.43,7585.69 5891.43,7486.43 5838,7433 5838,7036 5903,6971 6441,6971 6476.08,6935.92 6476.08,6767.92 6535,6709 6756,6709 6824,6777 v1(6843,6777)
  BottomLayer w6: v1(6843,6777) 7169,6777 7259,6867 7326,6867 7457,6998 R35.7@7555.84,6998
ED18: R37.5 U2.224 U8.34 | length 2672.5
  TopLayer w6: U2.224@5871.75,7585.69 5871.75,7495.75 5818,7442 5818,7028 5888,6958 6420,6958 6456.4,6921.6 6456.4,6763.6 6528,6692 6764,6692 6829,6757 v1(6859,6757) ; v1(7499,6981) 7547.84,6981 R37.5@7555.84,6989
  BottomLayer w6: v1(6859,6757) 7174,6757 7270,6853 7335,6853 7463,6981 v1(7499,6981)
ED19: R36.8 U2.223 U8.36 | length 2724.8
  TopLayer w6: U2.223@5852.06,7585.69 5852.06,7501.06 5800,7449 5800,7019 5876,6943 6380,6943 6417.02,6905.98 6417.02,6748.98 6491,6675 6776,6675 v1(6840,6739)
  BottomLayer w6: v1(6840,6739) 6917,6662 7221,6662 7333,6774 7387,6774 7487,6874 R36.8@7555.84,6874
ED20: R35.6 U2.222 U8.37 | length 2740
  TopLayer w6: U2.222@5832.38,7585.69 5832.38,7508.38 5783,7459 5783,7004 5858,6929 6366,6929 6397.34,6897.66 6397.34,6735.66 6476,6657 6797,6657 v1(6880,6740)
  BottomLayer w6: v1(6880,6740) 7182,6740 7281,6839 7343,6839 7466,6962 R35.6@7555.84,6962
ED21: R35.5 U2.219 U8.39 | length 2741.1
  TopLayer w6: U2.219@5773.32,7585.69 5773.32,7471.32 5764,7462 5764,6998 5847,6915 6340,6915 6357.97,6897.03 6357.97,6746.03 6467,6637 6804,6637 6870,6703 6883,6703 v1(6902,6722)
  BottomLayer w6: v1(6902,6722) 7190,6722 7292,6824 7354,6824 7456,6926 R35.5@7555.84,6926
ED22: R37.6 U2.218 U8.40 | length 2791.4
  TopLayer w6: U2.218@5753.64,7585.69 5753.64,7492.64 5745,7484 5745,6992 5836,6901 6326,6901 6338.28,6888.72 6338.28,6735.72 6456,6618 6809,6618 6875,6684 6904,6684 v1(6924,6704) ; v1(7464,6905) 7512,6953 R37.6@7555.84,6953
  BottomLayer w6: v1(6924,6704) 7200,6704 7302,6806 7365,6806 v1(7464,6905)
ED23: R36.6 U2.217 U8.42 | length 2796.8
  TopLayer w6: U2.217@5733.95,7585.69 5733.95,7491.95 5726,7484 5726,6981 5818,6889 6285,6889 6298.91,6875.09 6298.91,6731.09 6429,6601 6821,6601 v1(6886,6666)
  BottomLayer w6: v1(6886,6666) 6927,6625 7240,6625 7356,6741 7407,6741 7468,6802 R36.6@7555.84,6802
ED24: R37.7 U2.216 U8.45 | length 3363.4
  TopLayer w6: U2.216@5714.27,7585.69 5714.27,7492.27 5633,7411 5633,6573 5891,6315 6291,6315 6298.91,6322.91 ; U8.45@6298.91,6364 6298.91,6457.91 6424,6583 6829,6583 6892,6646 6904,6646 v1(6944,6686) ; v1(7492,6898) 7511,6917 R37.7@7555.84,6917
  BottomLayer w6: v1(6944,6686) 7209,6686 7313,6790 7384,6790 v1(7492,6898)
ED25: R36.7 U2.215 U8.47 | length 3411.4
  TopLayer w6: U2.215@5694.58,7585.69 5694.58,7495.58 5617,7418 5617,6567 5881,6303 6327,6303 6338.28,6314.28 6338.28,6469.28 6435.88,6566.88 6834.88,6566.88 6893,6625 6965.12,6625 v1(6983.12,6643)
  BottomLayer w6: v1(6983.12,6643) 7233,6643 7345,6755 7392,6755 7475,6838 R36.7@7555.84,6838
ED26: R37.8 U2.214 U8.48 | length 3491.7
  TopLayer w6: U2.214@5674.9,7585.69 5674.9,7500.9 5601,7427 5601,6556 5866,6291 6341,6291 6357.97,6307.97 6357.97,6466.97 6442,6551 6843,6551 6897,6605 v1(7023,6605) ; v1(7444,6743) 7444,6793 7532,6881 R37.8@7555.84,6881
  BottomLayer w6: v1(7023,6605) 7249,6605 7372,6728 7429,6728 v1(7444,6743)
ED27: R36.5 U2.213 U8.50 | length 3447.4
  TopLayer w6: U2.213@5655.21,7585.69 5655.21,7507.21 5586,7438 5586,6551 5858,6279 6365.34,6279 6397.34,6311 6397.34,6481.34 6450,6534 6848,6534 6898,6584 v1(7043,6584)
  BottomLayer w6: v1(7043,6584) 7255,6584 7384,6713 7466,6713 7519,6766 R36.5@7555.84,6766
ED28: R38.6 U2.208 U8.51 | length 3467.5
  TopLayer w6: U2.208@5556.79,7585.69 5556.79,7450.21 5572,7435 5572,6547 5852,6267 6371,6267 6417.02,6313.02 6417.02,6466.02 6467,6516 6854,6516 6900,6562 v1(7064,6562) ; v1(7463,6690) 7479,6706 7479,6732 7540,6793 R38.6@7555.84,6793
  BottomLayer w6: v1(7064,6562) 7260,6562 7388,6690 v1(7463,6690)
ED29: R38.5 U2.207 U8.53 | length 3502.7
  TopLayer w6: U2.207@5537.1,7585.69 5537.1,7433.9 5556,7415 5556,6541 5843,6254 6388,6254 6456.4,6322.4 6456.4,6442.4 6514,6500 6860,6500 6902,6542 v1(7083,6542) ; v1(7408.12,6668.12) 7465,6725 7465,6766 7528,6829 R38.5@7555.84,6829
  BottomLayer w6: v1(7083,6542) 7281,6542 ; 7282,6542 v1(7408.12,6668.12)
ED30: R38.8 U2.206 U8.54 | length 3463.2
  TopLayer w6: U2.206@5517.42,7585.69 5517.42,7424.58 5542,7400 5542,6535 5836,6241 6404,6241 6476.08,6313.08 6476.08,6429 6530.08,6483 6866,6483 6908,6525 v1(7109,6525) ; v1(7522,6721) R38.8@7555.84,6721
  BottomLayer w6: v1(7109,6525) 7326,6525 v1(7522,6721)
ED31: R38.7 U2.203 U8.56 | length 3574.9
  TopLayer w6: U2.203@5458.36,7585.69 5458.36,7457.64 5528,7388 5528,6525 5825,6228 6436,6228 6515.45,6307.45 6515.45,6439.45 6543,6467 6883,6467 v1(6920,6504) ; v1(7492,6655) 7492,6720 7529,6757 R38.7@7555.84,6757
  BottomLayer w6: v1(6920,6504) 7341,6504 v1(7492,6655)
EMU0: J1.13 U1.A15 | length 1067.8
  TopLayer w6: U1.A15@8414.82,6834 8414.82,6634.18 8651,6398 8721,6398 8828,6291 8828,6266 8863,6231 9029,6231 J1.13@9080,6180
EMU1: J1.14 U1.C14 | length 1073.9
  TopLayer w6: U1.C14@8454.19,6912.74 8434,6892.55 8434,6644 8659,6419 8740,6419 8822,6337 9023,6337 J1.14@9080,6280
FPGA_ASDO: JP5.9 U2.37 U5.5 | length 875.8
  TopLayer w6: U2.37@6274.31,8381.95 6362.05,8381.95 v1(6466,8278)
  BottomLayer w6: v1(6466,8278) 6686,8278 6705,8259 6705,8147 6620,8062 JP5.9@6620,7900
FPGA_IO41: JP12.1 U2.41 | length 545.2
  TopLayer w6: U2.41@6274.31,8460.69 6623.69,8460.69 6760,8597 JP12.1@6760,8600
FPGA_IO42: JP12.2 U2.42 | length 465.7
  TopLayer w6: U2.42@6274.31,8480.38 6592.38,8480.38 6660,8548 JP12.2@6660,8600
FPGA_IO43: JP12.3 U2.43 | length 611.9
  TopLayer w6: U2.43@6274.31,8500.06 6569.06,8500.06 6605,8536 6605,8610 6643,8648 6708,8648 JP12.3@6760,8700
FPGA_IO44: JP12.4 U2.44 | length 507.2
  TopLayer w6: U2.44@6274.31,8519.75 6559.75,8519.75 6583,8543 6583,8623 JP12.4@6660,8700
FPGA_NCSO: JP5.8 U2.24 U5.1 | length 1009.8
  TopLayer w6: U2.24@6276.35,8124 U2.24@6274.31,8126.05 6472.95,8126.05 6558,8041 6558,7877 6586,7849 6671,7849 JP5.8@6720,7800
  BottomLayer w6: JP5.8@6720,7800 6773,7853 6844,7853 6873,7882 6873,7999.64 U5.1@6855,8017.64
FPGA_PLLOUT: R12.1 U2.39 | length 1533.3
  TopLayer w6: U2.39@6274.31,8421.32 6318.68,8421.32 v1(6328,8412)
  BottomLayer w6: v1(6328,8412) 6328,8410 6421,8317 6907,8317 7144,8080 7144,7795 7225,7714 R12.1@7346.54,7714
GCLK1: R24.2 U2.29 | length 214.1
  TopLayer w12: U2.29@6274.31,8224.47 6482.06,8224.47 R24.2@6486.54,8220
GGND: FB6.1 FB7.1 FB8.1 pad.0 pad.2@4140,6217 pad.10 pad.11 pad.12 | length 1936.5
  TopLayer w12: v3(4583,6035) FB8.1@4583,6109.54 ; pad.10@5183,6046 5183,6075 5197,6089 5458,6089 pad.11@5496,6051 ; v3(7480,6033) FB7.1@7480,6106.54 8727.46,6106.54 pad.12@8801,6033 ; v3(9333.46,6026.54) FB6.1@9333.46,6100
  other v2: 10041,6014 9046,6021 9735,6024 6211,6025 4245,6028 4807,6028 6996,6029 5030,6030 4065,6031 4421,6032 5593,6033 5819,6033 6528,6033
